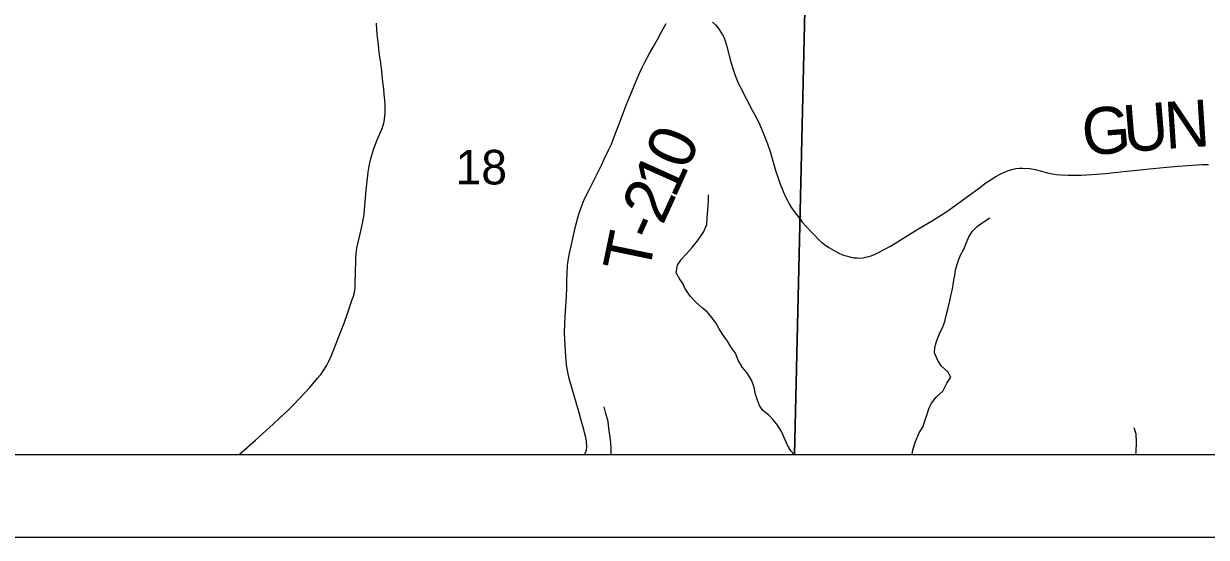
# Model space of a CAD drawing. Extents: x 0 to 34, y 0 to 22.
# Drawn here: x 6.594 to 8.027, y 14 to 14.622 of the extents above; entities that cross this region are included whole.
import ezdxf

# ---------------------------------------------------------------- set-up
doc = ezdxf.new("R2010")
doc.units = 0
for name, color, linetype in [('GM_X_Corporation', 7, 'Continuous'), ('GM_X_County_Road_Text', 7, 'Continuous'), ('GM_X_Interchange_Ramps', 7, 'Continuous'), ('GM_X_Interstate_Route', 7, 'Continuous'), ('GM_X_Major_Lake', 7, 'Continuous'), ('GM_X_Section', 7, 'Continuous'), ('GM_X_Township_Road_Text', 7, 'Continuous'), ('GM_X_Unincorporated_Text', 7, 'Continuous'), ('SH_Cut_Line', 7, 'Continuous'), ('SH_Data', 7, 'Continuous')]:
    doc.layers.add(name, color=color, linetype=linetype)

msp = doc.modelspace()

# ---------------------------------------------------------------- linework, layer by layer
at = {"layer": 'GM_X_Corporation'}
msp.add_lwpolyline([(7.4291, 14.6234), (7.4325, 14.6202), (7.4352, 14.6173), (7.4371, 14.6146), (7.4392, 14.6112), (7.4411, 14.6082), (7.443, 14.6043), (7.4446, 14.5995), (7.4459, 14.5956), (7.4509, 14.5767), (7.4529, 14.5697), (7.4562, 14.5599), (7.458, 14.555), (7.4603, 14.5496), (7.4625, 14.545), (7.4772, 14.517), (7.4805, 14.5111), (7.4847, 14.5028), (7.4883, 14.4944), (7.4903, 14.4895), (7.4956, 14.4762), (7.4987, 14.4667), (7.5059, 14.4426), (7.5084, 14.4348), (7.5107, 14.4285), (7.5151, 14.4177), (7.5171, 14.413), (7.5193, 14.4083), (7.5221, 14.4034), (7.5248, 14.3989), (7.5279, 14.3943), (7.5351, 14.3848), (7.5378, 14.3814), (7.5482, 14.37), (7.5529, 14.3651), (7.558, 14.3601), (7.5616, 14.3568), (7.5648, 14.3543), (7.57, 14.3506), (7.5726, 14.3491), (7.5784, 14.3458), (7.5838, 14.3432), (7.5879, 14.3415), (7.5926, 14.3401), (7.5965, 14.3389), (7.6006, 14.3383), (7.6041, 14.3381), (7.6077, 14.3379), (7.6115, 14.3383), (7.6145, 14.3389), (7.6186, 14.3399), (7.6214, 14.3408), (7.6262, 14.3428), (7.6311, 14.345), (7.637, 14.3483), (7.6445, 14.3525), (7.6779, 14.3727), (7.6942, 14.3825), (7.7119, 14.3936), (7.7156, 14.3961), (7.7408, 14.4144), (7.7507, 14.4217), (7.7603, 14.4288), (7.7665, 14.4328), (7.7724, 14.4365), (7.7768, 14.439), (7.7814, 14.4413), (7.7857, 14.4431), (7.789, 14.4442), (7.7933, 14.4456), (7.7966, 14.4461), (7.8011, 14.4468), (7.8047, 14.4469), (7.8135, 14.4464), (7.82, 14.4452), (7.8319, 14.4418), (7.8367, 14.4407), (7.8456, 14.4392), (7.851, 14.4387), (7.8597, 14.4382), (7.8692, 14.4383), (7.8758, 14.4384), (7.8887, 14.4389), (7.905, 14.4404), (7.9152, 14.4415), (7.9392, 14.4439), (7.9626, 14.4463), (7.9796, 14.4479), (7.9931, 14.4492), (8.0048, 14.4501), (8.0221, 14.451), (8.0299, 14.4513)], dxfattribs=at)
at = {"layer": 'GM_X_Interchange_Ramps'}
msp.add_lwpolyline([(6.5113, 14.1), (8.9, 14.1), (8.9, 17.8921), (8.5492, 17.9006), (8.3297, 17.9059), (7.6027, 17.9156), (6.5943, 17.9356), (6.5883, 17.471), (6.5647, 16.5359), (6.5572, 16.1864), (6.5411, 15.4243), (6.5389, 15.3228)], close=True, dxfattribs=at)
at = {"layer": 'GM_X_Interstate_Route'}
for points in [[(6.8554, 14.1), (6.8753, 14.1177), (6.8966, 14.1367), (6.9045, 14.1441), (6.9145, 14.1535), (6.921, 14.1599), (6.9284, 14.1674), (6.9349, 14.1743), (6.9411, 14.1814), (6.9506, 14.1927), (6.9543, 14.1971), (6.9584, 14.2031), (6.9617, 14.2084), (6.9641, 14.213), (6.967, 14.2191), (6.971, 14.2291), (6.9764, 14.2428), (6.9826, 14.2592), (6.9869, 14.271), (6.9925, 14.2877), (6.994, 14.292), (6.9951, 14.2961), (6.996, 14.3017), (6.9962, 14.3063), (6.9964, 14.3219), (6.9968, 14.3329), (6.9969, 14.3381), (6.9974, 14.3434), (6.9983, 14.35), (6.9995, 14.3552), (7.0011, 14.362), (7.0043, 14.3761), (7.0054, 14.3819), (7.0069, 14.3908), (7.0075, 14.3966), (7.0096, 14.4199), (7.0118, 14.4418), (7.0131, 14.4493), (7.0147, 14.4567), (7.0161, 14.4626), (7.0188, 14.4704), (7.0227, 14.4809), (7.0288, 14.4949), (7.0301, 14.4989), (7.0311, 14.5026), (7.0317, 14.5061), (7.0322, 14.5097), (7.0324, 14.5131), (7.0323, 14.5234), (7.0319, 14.5292), (7.0313, 14.5361), (7.0307, 14.5424), (7.0293, 14.5545), (7.0282, 14.5639), (7.0274, 14.5706), (7.0266, 14.5771), (7.0257, 14.584), (7.0249, 14.5903), (7.0242, 14.5963), (7.0235, 14.6025), (7.0228, 14.6088), (7.0223, 14.6147), (7.022, 14.6221)], [(7.2738, 14.1), (7.2743, 14.101), (7.2754, 14.1034), (7.2763, 14.1058), (7.2768, 14.1091), (7.2763, 14.1166), (7.2755, 14.1208), (7.2741, 14.1268), (7.2732, 14.1305), (7.2695, 14.143), (7.2673, 14.1506), (7.2645, 14.1601), (7.2555, 14.192), (7.2536, 14.2), (7.2522, 14.2089), (7.2517, 14.2134), (7.2508, 14.225), (7.2504, 14.2324), (7.2499, 14.248), (7.2505, 14.2675), (7.2521, 14.2912), (7.2524, 14.302), (7.2525, 14.3108), (7.253, 14.3197), (7.2534, 14.3284), (7.2541, 14.3351), (7.2559, 14.344), (7.2574, 14.3506), (7.2605, 14.3654), (7.2625, 14.3743), (7.2664, 14.3882), (7.268, 14.3933), (7.2699, 14.399), (7.2723, 14.4054), (7.2744, 14.4102), (7.279, 14.4195), (7.2858, 14.4327), (7.295, 14.4513), (7.2979, 14.4576), (7.303, 14.4686), (7.3065, 14.4759), (7.3086, 14.4815), (7.317, 14.5035), (7.3212, 14.5141), (7.3246, 14.5228), (7.3304, 14.5373), (7.334, 14.5463), (7.3402, 14.5609), (7.3434, 14.5678), (7.347, 14.5748), (7.3532, 14.5861), (7.3577, 14.5938), (7.3623, 14.6025), (7.3671, 14.6115), (7.3728, 14.6217)]]:
    msp.add_lwpolyline(points, dxfattribs=at)
at = {"layer": 'GM_X_Township_Road_Text'}
for points in [[(7.5278, 14.1), (7.5238, 14.1046), (7.5199, 14.1114), (7.5128, 14.128), (7.507, 14.1367), (7.502, 14.1427), (7.497, 14.1483), (7.4901, 14.1535), (7.4859, 14.1595), (7.4835, 14.166), (7.4811, 14.1728), (7.4795, 14.1815), (7.4763, 14.1902), (7.4705, 14.1993), (7.4655, 14.2053), (7.4601, 14.2143), (7.4569, 14.2227), (7.4519, 14.2294), (7.4473, 14.2374), (7.4411, 14.246), (7.4372, 14.2524), (7.4329, 14.2596), (7.4279, 14.2664), (7.4225, 14.2728), (7.4168, 14.2772), (7.4087, 14.2847), (7.4018, 14.2918), (7.3956, 14.3016), (7.3929, 14.3073), (7.3886, 14.3137), (7.3851, 14.3201), (7.3865, 14.3293), (7.3913, 14.3366), (7.3976, 14.3432), (7.4043, 14.3505), (7.4107, 14.3586), (7.4181, 14.3694), (7.4221, 14.3786), (7.4227, 14.3866), (7.4234, 14.3957), (7.4237, 14.4014), (7.424, 14.4075), (7.4242, 14.4144)], [(7.6708, 14.1), (7.6718, 14.1057), (7.6751, 14.116), (7.6795, 14.1264), (7.6843, 14.134), (7.6861, 14.1409), (7.6883, 14.1467), (7.6915, 14.1566), (7.6945, 14.1624), (7.7004, 14.1701), (7.7079, 14.1767), (7.713, 14.1866), (7.7179, 14.1939), (7.714, 14.2003), (7.7063, 14.2071), (7.702, 14.2139), (7.6981, 14.2233), (7.6984, 14.2298), (7.7006, 14.2371), (7.7038, 14.2455), (7.7079, 14.2547), (7.7104, 14.2612), (7.7122, 14.2684), (7.7144, 14.2776), (7.7165, 14.286), (7.7179, 14.2921), (7.7194, 14.2986), (7.7208, 14.3055), (7.7214, 14.3112), (7.7225, 14.3169), (7.7235, 14.3238), (7.7275, 14.3364), (7.7301, 14.3422), (7.7334, 14.3487), (7.7359, 14.3548), (7.7396, 14.3636), (7.744, 14.3705), (7.7496, 14.3763), (7.7556, 14.3806), (7.765, 14.3865)], [(7.3061, 14.1), (7.3061, 14.1012), (7.3064, 14.1073), (7.3059, 14.1149), (7.3042, 14.1263), (7.3034, 14.1316), (7.3025, 14.14), (7.2997, 14.1498), (7.2977, 14.1578)], [(7.9418, 14.1), (7.9422, 14.1026), (7.9428, 14.1155), (7.9422, 14.1247), (7.9399, 14.1326)]]:
    msp.add_lwpolyline(points, dxfattribs=at)
at = {"layer": 'GM_X_Unincorporated_Text'}
for points in [[(6.5122, 14.1), (7.5285, 14.1), (7.5466, 14.8803), (6.5307, 14.8925)], [(7.5285, 14.1), (8.5434, 14.1), (8.5685, 14.859), (7.5466, 14.8803)]]:
    msp.add_lwpolyline(points, close=True, dxfattribs=at)
at = {"layer": 'SH_Cut_Line'}
msp.add_lwpolyline([(2.1, 17.9098), (2.1, 14.1), (8.9, 14.1), (8.9, 17.8921), (8.5492, 17.9006), (8.3297, 17.9059), (7.6027, 17.9156), (6.5943, 17.9356), (6.24, 17.9427), (6.0729, 17.9463), (5.6339, 17.9555), (5.3871, 17.9608), (4.994, 17.969), (4.9368, 17.9702), (4.9267, 17.9702), (4.5919, 17.9719), (4.4481, 17.9728), (4.1825, 17.9744), (3.7128, 17.9822), (3.7063, 17.8588), (3.604, 17.8577), (2.9484, 17.8857), (2.6711, 17.8975), (2.4376, 17.9025)], close=True, dxfattribs=at)
at = {"layer": 'SH_Data'}
for p, q in [((2.1, 14.1), (8.9, 14.1)), ((2, 14), (9, 14))]:
    msp.add_line(p, q, dxfattribs=at)

# ---------------------------------------------------------------- texts
at = {"layer": 'GM_X_County_Road_Text'}
msp.add_text('18', height=0.04186, rotation=0, dxfattribs=at).set_placement((7.1178, 14.427))
at = {"layer": 'GM_X_Major_Lake'}
for s, rotation, p in [('G', 4.763, (7.8788, 14.4617)), ('U', 4.6826, (7.9286, 14.4658)), ('N', 3.7402, (7.9782, 14.4699))]:
    msp.add_text(s, height=0.0568, rotation=rotation, dxfattribs=at).set_placement(p)
at = {"layer": 'GM_X_Section'}
for s, rotation, p in [('0', 67.5626, (7.3984, 14.4426)), ('1', 65.7938, (7.3833, 14.4089)), ('2', 65.4135, (7.3686, 14.3767)), ('T', 78.274, (7.3515, 14.317)), ('-', 65.9701, (7.3592, 14.3556))]:
    msp.add_text(s, height=0.0568, rotation=rotation, dxfattribs=at).set_placement(p)

doc.saveas('drawing.dxf')
